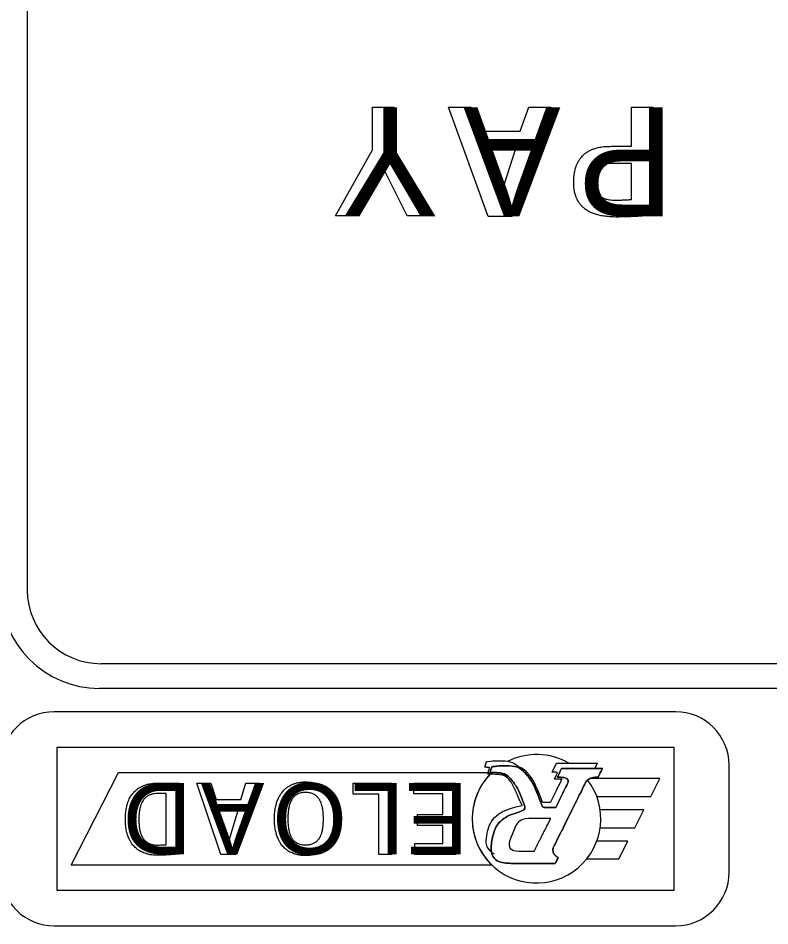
# Model space of a CAD drawing. Extents: x -102643 to -98250, y 54554 to 62384.
# Drawn here: x -102203.2 to -101962.7, y 58225.9 to 58516.5 of the extents above; entities that cross this region are included whole.
import ezdxf

# ---------------------------------------------------------------- set-up
doc = ezdxf.new("R2010")
doc.units = 0
doc.layers.add('SignPanel', color=7, linetype='Continuous')

msp = doc.modelspace()

# ---------------------------------------------------------------- linework, layer by layer
at = {"layer": 'SignPanel'}
for p, q in [((-102200.3, 58701.51), (-102200.3, 58333.46)), ((-101672.5, 58309.8), (-102176.64, 58309.8)), ((-101672.5, 58301.91), (-102177.25, 58301.91)), ((-101992.86, 58294.42), (-102191.66, 58294.41)), ((-101993.32, 58282.99), (-102190.83, 58282.98)), ((-102190.83, 58282.98), (-102190.83, 58237.28)), ((-101993.32, 58237.29), (-101993.32, 58282.99)), ((-101975.72, 58243.01), (-101975.73, 58277.28)), ((-102035.4, 58265.46), (-102032.83, 58265.46)), ((-102190.83, 58237.28), (-101993.32, 58237.29)), ((-102191.66, 58225.86), (-101992.86, 58225.87))]:
    msp.add_line(p, q, dxfattribs=at)
for points in [[(-102089.78, 58474.39), (-102089.78, 58488.01), (-102083.01, 58488.01), (-102083.01, 58474.6), (-102071.07, 58453.17), (-102078.73, 58453.17), (-102086.46, 58468.54), (-102094.22, 58453.17), (-102101.63, 58453.17), (-102089.78, 58474.39)], [(-102058.23, 58488.01), (-102055.48, 58480.35), (-102042.53, 58480.35), (-102039.85, 58488.01), (-102032.74, 58488.01), (-102045.17, 58453.05), (-102052.83, 58453.05), (-102065.46, 58488.01), (-102058.23, 58488.01)], [(-102013.49, 58475.48), (-102006.94, 58475.48), (-102006.94, 58488.01), (-102000.17, 58488.01), (-102000.17, 58453.43)], [(-102049.04, 58459.57), (-102048.87, 58459.56), (-102043.96, 58474.76), (-102053.95, 58474.76), (-102049.04, 58459.57)], [(-102006.94, 58458.43), (-102006.94, 58470.02), (-102012.17, 58470.02)], [(-102053.86, 58276.62), (-102053.34, 58278.44), (-102052.98, 58278.49)], [(-102032.35, 58275.09), (-102030.93, 58277.94), (-102017.9, 58277.94), (-102018.72, 58276.29)], [(-102051.58, 58245.29), (-102186.26, 58245.28), (-102171.13, 58274.99), (-102051.58, 58274.99)], [(-102018.07, 58267.29), (-102000.8, 58267.29), (-101997.89, 58273), (-102020.25, 58273)], [(-102158.44, 58271.56), (-102151.7, 58271.56), (-102151.7, 58248.85)], [(-102141.55, 58271.56), (-102139.89, 58266.34), (-102131.98, 58266.34), (-102130.32, 58271.56), (-102126.02, 58271.56), (-102133.51, 58248.66), (-102138.33, 58248.66), (-102145.98, 58271.56), (-102141.55, 58271.56)], [(-102083.68, 58271.56), (-102083.68, 58248.71), (-102087.79, 58248.71), (-102087.79, 58268.07), (-102095.98, 58268.07), (-102095.98, 58271.56), (-102083.68, 58271.56)], [(-102063.18, 58271.57), (-102063.18, 58248.71), (-102076.26, 58248.71), (-102076.26, 58252.21), (-102067.29, 58252.21), (-102067.29, 58257.96), (-102075.4, 58257.96), (-102075.4, 58261.49), (-102067.29, 58261.49), (-102067.29, 58268.15), (-102076.61, 58268.15), (-102076.61, 58271.56), (-102063.18, 58271.57)], [(-102155.81, 58251.85), (-102155.81, 58268.2)], [(-102016.99, 58257.29), (-102005.9, 58257.29), (-102002.98, 58263), (-102016.99, 58263)], [(-102135.98, 58252.54), (-102135.87, 58252.54), (-102132.81, 58262.9), (-102139.04, 58262.9), (-102135.98, 58252.54)], [(-102021.3, 58247.29), (-102010.99, 58247.29), (-102008.08, 58253), (-102018.07, 58253)]]:
    msp.add_lwpolyline(points, dxfattribs=at)
for centre, radius, start, end in [((-102177.25, 58333.46), 31.55, 180, 270), ((-102176.64, 58333.46), 23.66, 180, 270), ((-102191.66, 58277.27), 17.14, 90.003, 180.003), ((-101992.86, 58277.28), 17.14, 0.003, 90.003), ((-102037.35, 58260.14), 20.57, 59.9596, 116.902), ((-102037.35, 58260.14), 20.57, 136.1816, 226.2418), ((-102037.35, 58260.14), 20.57, 136.1816, 37.2738), ((-102191.66, 58243), 17.14, 180.003, 270.003), ((-101992.86, 58243.01), 17.14, 270.003, 0.003)]:
    msp.add_arc(centre, radius, start, end, dxfattribs=at)
for points, degree in [([(-102025.44, 58463.95), (-102025.43, 58464.39), (-102025.41, 58465.63), (-102025.18, 58467.26), (-102024.83, 58468.59), (-102024.53, 58469.47), (-102024.17, 58470.29), (-102023.63, 58471.21), (-102023.11, 58471.91), (-102022.64, 58472.42), (-102022.14, 58472.91), (-102021.44, 58473.46), (-102020.5, 58474.04), (-102019.65, 58474.43), (-102018.72, 58474.78), (-102017.26, 58475.2), (-102015.42, 58475.45), (-102014, 58475.47), (-102013.49, 58475.48)], 3), ([(-102012.17, 58470.02), (-102012.64, 58470.01), (-102013.54, 58470), (-102014.53, 58469.9), (-102015.23, 58469.79), (-102015.69, 58469.67), (-102016.2, 58469.48), (-102016.59, 58469.27), (-102016.88, 58469.08), (-102017.15, 58468.87), (-102017.46, 58468.55), (-102017.78, 58468.1), (-102018, 58467.67), (-102018.15, 58467.29), (-102018.29, 58466.87), (-102018.46, 58466.13), (-102018.57, 58465.16), (-102018.58, 58464.44), (-102018.58, 58464.12)], 3), ([(-102011.73, 58452.84), (-102012.19, 58452.84), (-102013.56, 58452.86), (-102015.35, 58453.04), (-102017.07, 58453.34), (-102018.48, 58453.69), (-102019.79, 58454.19), (-102020.82, 58454.75), (-102021.46, 58455.16), (-102022.06, 58455.61), (-102022.76, 58456.24), (-102023.49, 58457.1), (-102024.02, 58457.9), (-102024.39, 58458.59), (-102024.73, 58459.33), (-102025.06, 58460.36), (-102025.38, 58461.97), (-102025.42, 58463.19), (-102025.44, 58463.95)], 3), ([(-102018.58, 58464.12), (-102018.58, 58463.85), (-102018.57, 58463.12), (-102018.46, 58462.18), (-102018.27, 58461.43), (-102018.11, 58460.97), (-102017.92, 58460.55), (-102017.63, 58460.1), (-102017.34, 58459.76), (-102017.08, 58459.53), (-102016.8, 58459.3), (-102016.41, 58459.06), (-102015.89, 58458.81), (-102015.41, 58458.65), (-102014.89, 58458.52), (-102014.06, 58458.36), (-102013.02, 58458.27), (-102012.22, 58458.26), (-102011.92, 58458.25)], 3), ([(-102011.92, 58458.25), (-102011.53, 58458.26), (-102010.74, 58458.26), (-102009.52, 58458.31), (-102008.25, 58458.36), (-102007.38, 58458.41), (-102006.94, 58458.43)], 3), ([(-102000.17, 58453.43), (-102001, 58453.35), (-102002.78, 58453.18), (-102005.6, 58453), (-102008.62, 58452.86), (-102010.69, 58452.84), (-102011.73, 58452.84)], 3), ([(-102052.98, 58278.49), (-102051.5, 58278.69), (-102050.55, 58278.74), (-102049.45, 58278.74), (-102046.63, 58278.74), (-102044.65, 58278.11), (-102043.11, 58276.82)], 3), ([(-102052.34, 58276.56), (-102052.84, 58276.6), (-102053.35, 58276.62), (-102053.86, 58276.62)], 2), ([(-102045.24, 58271.5), (-102045.42, 58271.76), (-102045.61, 58272.02), (-102045.8, 58272.25), (-102047.18, 58273.97), (-102049.56, 58274.39), (-102052.96, 58274.39), (-102052.96, 58274.39), (-102052.59, 58275.7), (-102052.34, 58276.56)], 3), ([(-102031.17, 58263.8), (-102031.17, 58263.8), (-102027.68, 58270.85), (-102027.68, 58270.85), (-102027.05, 58271.88), (-102027.5, 58273.44), (-102030.7, 58273.44), (-102030.7, 58273.44), (-102029.27, 58276.29), (-102029.27, 58276.29), (-102029.27, 58276.29), (-102016.24, 58276.29), (-102016.24, 58276.29), (-102016.24, 58276.29), (-102017.66, 58273.44), (-102017.66, 58273.44), (-102017.66, 58273.44), (-102018.07, 58273.44), (-102018.07, 58273.44), (-102018.07, 58273.44), (-102018.51, 58273.42), (-102018.51, 58273.42), (-102018.51, 58273.42), (-102018.88, 58273.38), (-102018.88, 58273.38), (-102018.88, 58273.38), (-102019.51, 58273.24), (-102019.51, 58273.24), (-102019.51, 58273.24), (-102019.99, 58273.11), (-102019.99, 58273.11), (-102019.99, 58273.11), (-102020.4, 58272.94), (-102020.4, 58272.94), (-102020.4, 58272.94), (-102020.69, 58272.78), (-102020.69, 58272.78), (-102020.69, 58272.78), (-102020.98, 58272.61), (-102020.98, 58272.61), (-102020.98, 58272.61), (-102021.27, 58272.34), (-102021.27, 58272.34), (-102021.27, 58272.34), (-102021.48, 58272.07), (-102021.48, 58272.07), (-102021.48, 58272.07), (-102021.55, 58271.91), (-102021.55, 58271.91), (-102021.55, 58271.91), (-102032.03, 58250.8), (-102032.03, 58250.8), (-102032.03, 58250.8), (-102032.07, 58250.5), (-102032.07, 58250.5), (-102032.07, 58250.5), (-102032.07, 58250.21), (-102032.07, 58250.21), (-102032.07, 58250.21), (-102032.07, 58249.99), (-102032.07, 58249.99), (-102032.07, 58249.99), (-102032.05, 58249.72), (-102032.05, 58249.72), (-102032.05, 58249.72), (-102031.97, 58249.4), (-102031.97, 58249.4), (-102031.97, 58249.4), (-102031.84, 58249.05), (-102031.84, 58249.05), (-102031.84, 58249.05), (-102031.7, 58248.82), (-102031.7, 58248.82), (-102031.7, 58248.82), (-102031.45, 58248.49), (-102031.45, 58248.49), (-102031.45, 58248.49), (-102031.11, 58248.2), (-102031.11, 58248.2), (-102031.11, 58248.2), (-102030.76, 58247.95), (-102030.76, 58247.95), (-102030.76, 58247.95), (-102030.41, 58247.74), (-102030.41, 58247.74), (-102030.41, 58247.74), (-102031.36, 58245.87), (-102031.36, 58245.87), (-102031.36, 58245.87), (-102044.17, 58245.87), (-102044.17, 58245.87), (-102049.99, 58245.87), (-102052.32, 58249.4), (-102051.51, 58253.52), (-102050.6, 58258.1), (-102046.22, 58261.68), (-102040.25, 58262.72), (-102041.55, 58265.15), (-102043.12, 58269.83), (-102045.35, 58272.61), (-102046.86, 58274.5), (-102049.51, 58274.96), (-102052.2, 58274.96), (-102052.2, 58274.96), (-102051.68, 58276.78), (-102051.68, 58276.78), (-102051.68, 58276.78), (-102051.32, 58276.83), (-102051.32, 58276.83), (-102049.84, 58277.03), (-102048.89, 58277.08), (-102047.8, 58277.08), (-102044.17, 58277.08), (-102041.94, 58276.04), (-102040.22, 58273.9), (-102038.23, 58271.42), (-102036.3, 58266.12), (-102035.34, 58263.8), (-102035.34, 58263.8), (-102031.17, 58263.8), (-102031.17, 58263.8)], 3), ([(-102031.17, 58263.8), (-102031.17, 58263.8), (-102027.68, 58270.85), (-102027.68, 58270.85), (-102027.05, 58271.88), (-102027.5, 58273.44), (-102030.7, 58273.44), (-102030.7, 58273.44), (-102029.27, 58276.29), (-102029.27, 58276.29), (-102029.27, 58276.29), (-102016.24, 58276.29), (-102016.24, 58276.29), (-102016.24, 58276.29), (-102017.66, 58273.44), (-102017.66, 58273.44), (-102017.66, 58273.44), (-102018.07, 58273.44), (-102018.07, 58273.44), (-102018.07, 58273.44), (-102018.51, 58273.42), (-102018.51, 58273.42), (-102018.51, 58273.42), (-102018.88, 58273.38), (-102018.88, 58273.38), (-102018.88, 58273.38), (-102019.51, 58273.24), (-102019.51, 58273.24), (-102019.51, 58273.24), (-102019.99, 58273.11), (-102019.99, 58273.11), (-102019.99, 58273.11), (-102020.4, 58272.94), (-102020.4, 58272.94), (-102020.4, 58272.94), (-102020.69, 58272.78), (-102020.69, 58272.78), (-102020.69, 58272.78), (-102020.98, 58272.61), (-102020.98, 58272.61), (-102020.98, 58272.61), (-102021.27, 58272.34), (-102021.27, 58272.34), (-102021.27, 58272.34), (-102021.48, 58272.07), (-102021.48, 58272.07), (-102021.48, 58272.07), (-102021.55, 58271.91), (-102021.55, 58271.91), (-102021.55, 58271.91), (-102032.03, 58250.8), (-102032.03, 58250.8), (-102032.03, 58250.8), (-102032.07, 58250.5), (-102032.07, 58250.5), (-102032.07, 58250.5), (-102032.07, 58250.21), (-102032.07, 58250.21), (-102032.07, 58250.21), (-102032.07, 58249.99), (-102032.07, 58249.99), (-102032.07, 58249.99), (-102032.05, 58249.72), (-102032.05, 58249.72), (-102032.05, 58249.72), (-102031.97, 58249.4), (-102031.97, 58249.4), (-102031.97, 58249.4), (-102031.84, 58249.05), (-102031.84, 58249.05), (-102031.84, 58249.05), (-102031.7, 58248.82), (-102031.7, 58248.82), (-102031.7, 58248.82), (-102031.45, 58248.49), (-102031.45, 58248.49), (-102031.45, 58248.49), (-102031.11, 58248.2), (-102031.11, 58248.2), (-102031.11, 58248.2), (-102030.76, 58247.95), (-102030.76, 58247.95), (-102030.76, 58247.95), (-102030.41, 58247.74), (-102030.41, 58247.74), (-102030.41, 58247.74), (-102031.36, 58245.87), (-102031.36, 58245.87), (-102031.36, 58245.87), (-102044.17, 58245.87), (-102044.17, 58245.87), (-102049.99, 58245.87), (-102052.32, 58249.4), (-102051.51, 58253.52), (-102050.6, 58258.1), (-102046.22, 58261.68), (-102040.25, 58262.72), (-102041.55, 58265.15), (-102043.12, 58269.83), (-102045.35, 58272.61), (-102046.86, 58274.5), (-102049.51, 58274.96), (-102052.2, 58274.96), (-102052.2, 58274.96), (-102051.68, 58276.78), (-102051.68, 58276.78), (-102051.68, 58276.78), (-102051.32, 58276.83), (-102051.32, 58276.83), (-102049.84, 58277.03), (-102048.89, 58277.08), (-102047.8, 58277.08), (-102044.17, 58277.08), (-102041.94, 58276.04), (-102040.22, 58273.9), (-102038.23, 58271.42), (-102036.3, 58266.12), (-102035.34, 58263.8), (-102035.34, 58263.8), (-102031.17, 58263.8), (-102031.17, 58263.8)], 3), ([(-102029.46, 58255.99), (-102030.94, 58253), (-102032.03, 58250.8), (-102032.03, 58250.8), (-102032.03, 58250.8), (-102032.07, 58250.5), (-102032.07, 58250.5), (-102032.07, 58250.5), (-102032.07, 58250.21), (-102032.07, 58250.21), (-102032.07, 58250.21), (-102032.07, 58249.99), (-102032.07, 58249.99), (-102032.07, 58249.99), (-102032.05, 58249.72), (-102032.05, 58249.72), (-102032.05, 58249.72), (-102031.97, 58249.4), (-102031.97, 58249.4), (-102031.97, 58249.4), (-102031.84, 58249.05), (-102031.84, 58249.05), (-102031.84, 58249.05), (-102031.7, 58248.82), (-102031.7, 58248.82), (-102031.7, 58248.82), (-102031.45, 58248.49), (-102031.45, 58248.49), (-102031.45, 58248.49), (-102031.11, 58248.2), (-102031.11, 58248.2), (-102031.11, 58248.2), (-102030.76, 58247.95), (-102030.76, 58247.95), (-102030.76, 58247.95), (-102030.41, 58247.74), (-102030.41, 58247.74), (-102030.41, 58247.74), (-102031.36, 58245.87), (-102031.36, 58245.87), (-102031.36, 58245.87), (-102044.17, 58245.87), (-102044.17, 58245.87), (-102049.99, 58245.87), (-102052.32, 58249.4), (-102051.51, 58253.52), (-102050.6, 58258.1), (-102046.22, 58261.68), (-102040.25, 58262.72), (-102041.55, 58265.15), (-102043.12, 58269.83), (-102045.35, 58272.61), (-102046.86, 58274.5), (-102049.51, 58274.96), (-102052.2, 58274.96), (-102052.2, 58274.96), (-102051.68, 58276.78), (-102051.68, 58276.78), (-102051.68, 58276.78), (-102051.32, 58276.83), (-102051.32, 58276.83), (-102049.84, 58277.03), (-102048.89, 58277.08), (-102047.8, 58277.08), (-102044.17, 58277.08), (-102041.94, 58276.04), (-102040.22, 58273.9), (-102038.23, 58271.42), (-102036.3, 58266.12), (-102035.34, 58263.8), (-102035.34, 58263.8), (-102031.17, 58263.8), (-102031.17, 58263.8)], 3), ([(-102051.76, 58276.5), (-102051.91, 58275.99), (-102052.2, 58274.96), (-102052.2, 58274.96), (-102050.14, 58274.96), (-102048.11, 58274.69), (-102046.59, 58273.72)], 3), ([(-102035.4, 58265.46), (-102036.36, 58267.87), (-102038.03, 58272.08), (-102039.78, 58274.26), (-102040.69, 58275.39), (-102041.77, 58276.25), (-102043.11, 58276.82)], 3), ([(-102041.76, 58275.41), (-102041.2, 58274.99), (-102040.69, 58274.49), (-102040.22, 58273.9), (-102038.62, 58271.9), (-102037.06, 58268.08), (-102036.01, 58265.46)], 3), ([(-102030.61, 58274.88), (-102031.07, 58275.02), (-102031.64, 58275.09), (-102032.35, 58275.09)], 2), ([(-102029.25, 58272.67), (-102029.8, 58272.79), (-102030.58, 58272.86), (-102031.62, 58272.86), (-102031.62, 58272.86), (-102031.11, 58273.88), (-102030.61, 58274.88)], 3), ([(-102031.17, 58263.8), (-102031.17, 58263.8), (-102027.68, 58270.85), (-102027.68, 58270.85), (-102027.05, 58271.88), (-102027.5, 58273.44), (-102030.7, 58273.44), (-102030.7, 58273.44), (-102029.27, 58276.29), (-102029.27, 58276.29), (-102029.27, 58276.29), (-102016.24, 58276.29), (-102016.24, 58276.29), (-102016.24, 58276.29), (-102017.66, 58273.44), (-102017.66, 58273.44), (-102017.66, 58273.44), (-102018.07, 58273.44), (-102018.07, 58273.44), (-102018.07, 58273.44), (-102018.51, 58273.42), (-102018.51, 58273.42), (-102018.51, 58273.42), (-102018.88, 58273.38), (-102018.88, 58273.38), (-102018.88, 58273.38), (-102019.51, 58273.24), (-102019.51, 58273.24), (-102019.51, 58273.24), (-102019.99, 58273.11), (-102019.99, 58273.11), (-102019.99, 58273.11), (-102020.4, 58272.94), (-102020.4, 58272.94), (-102020.4, 58272.94), (-102020.69, 58272.78), (-102020.69, 58272.78), (-102020.69, 58272.78), (-102020.98, 58272.61), (-102020.98, 58272.61), (-102020.98, 58272.61), (-102021.27, 58272.34), (-102021.27, 58272.34), (-102021.27, 58272.34), (-102021.48, 58272.07), (-102021.48, 58272.07), (-102021.48, 58272.07), (-102021.55, 58271.91), (-102021.55, 58271.91), (-102021.55, 58271.91), (-102026.33, 58262.29), (-102029.44, 58256.03)], 3), ([(-102030.07, 58274.68), (-102030.4, 58274.03), (-102030.7, 58273.44), (-102030.7, 58273.44), (-102030.06, 58273.44), (-102029.53, 58273.37), (-102029.09, 58273.27)], 3), ([(-102121.21, 58260.12), (-102121.2, 58260.56), (-102121.18, 58261.82), (-102120.97, 58263.47), (-102120.59, 58265.01), (-102120.18, 58266.22), (-102119.65, 58267.34), (-102119.08, 58268.21), (-102118.67, 58268.74), (-102118.24, 58269.24), (-102117.64, 58269.81), (-102116.86, 58270.41), (-102116.14, 58270.83), (-102115.54, 58271.12), (-102114.9, 58271.39), (-102113.87, 58271.7), (-102112.58, 58271.92), (-102111.63, 58271.94), (-102111.23, 58271.95)], 3), ([(-102111.23, 58271.95), (-102110.83, 58271.94), (-102109.87, 58271.92), (-102108.58, 58271.7), (-102107.54, 58271.39), (-102106.9, 58271.12), (-102106.3, 58270.83), (-102105.58, 58270.41), (-102104.8, 58269.81), (-102104.21, 58269.24), (-102103.78, 58268.74), (-102103.37, 58268.21), (-102102.81, 58267.34), (-102102.28, 58266.22), (-102101.87, 58265.01), (-102101.49, 58263.47), (-102101.28, 58261.83), (-102101.26, 58260.56), (-102101.25, 58260.12)], 3), ([(-102032.83, 58265.46), (-102032.83, 58265.46), (-102029.34, 58272.51), (-102029.34, 58272.51), (-102029.31, 58272.56), (-102029.28, 58272.61), (-102029.25, 58272.67)], 3), ([(-102168.89, 58260.02), (-102168.88, 58260.46), (-102168.86, 58261.7), (-102168.65, 58263.31), (-102168.28, 58264.82), (-102167.99, 58265.69), (-102167.64, 58266.5), (-102167.24, 58267.25), (-102166.76, 58267.95), (-102166.34, 58268.47), (-102165.89, 58268.95), (-102165.28, 58269.51), (-102164.45, 58270.08), (-102163.71, 58270.49), (-102163.07, 58270.77), (-102162.39, 58271.02), (-102161.28, 58271.33), (-102159.9, 58271.53), (-102158.87, 58271.55), (-102158.44, 58271.56)], 3), ([(-102041.9, 58264.38), (-102042.84, 58266.12), (-102043.9, 58269), (-102045.25, 58271.52)], 2), ([(-102158.15, 58268.27), (-102158.41, 58268.26), (-102159.14, 58268.25), (-102159.98, 58268.12), (-102160.64, 58267.93), (-102160.95, 58267.83), (-102161.34, 58267.67), (-102161.8, 58267.42), (-102162.31, 58267.06), (-102162.69, 58266.7), (-102162.97, 58266.38), (-102163.23, 58266.03), (-102163.59, 58265.44), (-102163.93, 58264.65), (-102164.19, 58263.78), (-102164.44, 58262.61), (-102164.57, 58261.31), (-102164.58, 58260.29), (-102164.59, 58259.92)], 3), ([(-102155.81, 58268.2), (-102156.04, 58268.21), (-102156.46, 58268.24), (-102157.05, 58268.26), (-102157.61, 58268.27), (-102157.97, 58268.27), (-102158.15, 58268.27)], 3), ([(-102111.26, 58268.56), (-102111.4, 58268.56), (-102111.78, 58268.56), (-102112.4, 58268.49), (-102113.1, 58268.33), (-102113.62, 58268.13), (-102114.01, 58267.93), (-102114.36, 58267.71), (-102114.77, 58267.39), (-102115.21, 58266.94), (-102115.52, 58266.52), (-102115.8, 58266.06), (-102116.16, 58265.35), (-102116.46, 58264.44), (-102116.71, 58263.2), (-102116.87, 58261.83), (-102116.9, 58260.7), (-102116.91, 58260.12)], 3), ([(-102105.52, 58260.12), (-102105.54, 58260.71), (-102105.56, 58261.84), (-102105.72, 58263.22), (-102105.98, 58264.46), (-102106.25, 58265.26), (-102106.55, 58265.89), (-102106.71, 58266.18), (-102106.94, 58266.54), (-102107.26, 58266.96), (-102107.7, 58267.41), (-102108.12, 58267.72), (-102108.47, 58267.94), (-102108.86, 58268.14), (-102109.39, 58268.34), (-102110.09, 58268.49), (-102110.73, 58268.56), (-102111.12, 58268.56), (-102111.26, 58268.56)], 3), ([(-102050.79, 58248.77), (-102052.92, 58250.16), (-102053.68, 58252.55), (-102053.16, 58255.18), (-102052.26, 58259.75), (-102047.87, 58263.33), (-102041.9, 58264.38)], 3), ([(-102111.23, 58248.35), (-102111.63, 58248.36), (-102112.59, 58248.38), (-102113.89, 58248.6), (-102114.93, 58248.92), (-102115.57, 58249.18), (-102116.18, 58249.47), (-102116.89, 58249.89), (-102117.68, 58250.49), (-102118.26, 58251.06), (-102118.69, 58251.56), (-102119.1, 58252.09), (-102119.65, 58252.96), (-102120.18, 58254.07), (-102120.59, 58255.28), (-102120.97, 58256.81), (-102121.18, 58258.43), (-102121.2, 58259.68), (-102121.21, 58260.12)], 3), ([(-102116.91, 58260.12), (-102116.9, 58259.53), (-102116.87, 58258.41), (-102116.71, 58257.03), (-102116.46, 58255.8), (-102116.19, 58255.01), (-102115.89, 58254.39), (-102115.73, 58254.11), (-102115.51, 58253.75), (-102115.19, 58253.34), (-102114.75, 58252.9), (-102114.34, 58252.59), (-102113.99, 58252.38), (-102113.61, 58252.18), (-102113.08, 58251.99), (-102112.39, 58251.84), (-102111.77, 58251.77), (-102111.37, 58251.77), (-102111.24, 58251.77)], 3), ([(-102111.24, 58251.77), (-102111.1, 58251.77), (-102110.71, 58251.77), (-102110.08, 58251.84), (-102109.38, 58251.99), (-102108.85, 58252.19), (-102108.46, 58252.39), (-102108.1, 58252.61), (-102107.69, 58252.92), (-102107.24, 58253.36), (-102106.92, 58253.77), (-102106.7, 58254.13), (-102106.32, 58254.82), (-102106, 58255.71), (-102105.72, 58257.06), (-102105.56, 58258.42), (-102105.54, 58259.54), (-102105.52, 58260.12)], 3), ([(-102101.25, 58260.12), (-102101.26, 58259.68), (-102101.28, 58258.43), (-102101.49, 58256.81), (-102101.87, 58255.28), (-102102.28, 58254.07), (-102102.81, 58252.96), (-102103.36, 58252.09), (-102103.77, 58251.56), (-102104.19, 58251.06), (-102104.78, 58250.49), (-102105.57, 58249.89), (-102106.28, 58249.47), (-102106.89, 58249.18), (-102107.53, 58248.92), (-102108.57, 58248.6), (-102109.87, 58248.38), (-102110.83, 58248.36), (-102111.23, 58248.35)], 3), ([(-102033.83, 58258.21), (-102033.23, 58259.41), (-102032.81, 58260.25), (-102032.81, 58260.25), (-102032.81, 58260.25), (-102034.54, 58260.25), (-102034.54, 58260.25), (-102040.26, 58260.25), (-102043.34, 58259.83), (-102045.27, 58254.86), (-102046.6, 58251.41), (-102045.12, 58249.73), (-102040.85, 58249.73), (-102040.85, 58249.73), (-102038.11, 58249.73), (-102038.11, 58249.73)], 3), ([(-102158.57, 58248.46), (-102158.98, 58248.47), (-102159.96, 58248.49), (-102161.28, 58248.69), (-102162.35, 58248.98), (-102163.01, 58249.22), (-102163.64, 58249.49), (-102164.37, 58249.88), (-102165.19, 58250.44), (-102165.8, 58250.99), (-102166.25, 58251.46), (-102166.67, 58251.97), (-102167.15, 58252.67), (-102167.73, 58253.74), (-102168.19, 58254.94), (-102168.64, 58256.64), (-102168.86, 58258.3), (-102168.88, 58259.57), (-102168.89, 58260.02)], 3), ([(-102164.59, 58259.92), (-102164.58, 58259.4), (-102164.55, 58258.38), (-102164.4, 58257.12), (-102164.17, 58255.94), (-102163.88, 58255.06), (-102163.53, 58254.35), (-102163.26, 58253.88), (-102162.94, 58253.45), (-102162.49, 58252.99), (-102162.07, 58252.66), (-102161.7, 58252.42), (-102161.3, 58252.2), (-102160.74, 58251.98), (-102160, 58251.81), (-102159.33, 58251.74), (-102158.91, 58251.74), (-102158.77, 58251.74)], 3), ([(-102038.11, 58249.73), (-102038.11, 58249.73), (-102035.4, 58255.1), (-102033.85, 58258.17)], 2), ([(-102158.77, 58251.74), (-102158.52, 58251.74), (-102158.03, 58251.74), (-102157.29, 58251.76), (-102156.55, 58251.79), (-102156.06, 58251.83), (-102155.81, 58251.85)], 3), ([(-102151.7, 58248.85), (-102151.96, 58248.82), (-102152.5, 58248.78), (-102153.34, 58248.7), (-102154.2, 58248.62), (-102155.09, 58248.57), (-102155.99, 58248.53), (-102156.88, 58248.49), (-102157.74, 58248.47), (-102158.3, 58248.46), (-102158.57, 58248.46)], 3)]:
    msp.add_open_spline(points, degree=degree, dxfattribs=at)

# ---------------------------------------------------------------- texts
for s, height, rotation, p in [('Y', 34.96, 180, (-102068.62, 58488.01)), ('Y', 34.96, 180, (-102068.62, 58488.01)), ('A', 34.96, 180, (-102029.61, 58488.01)), ('A', 34.96, 180, (-102029.61, 58488.01)), ('P', 34.96, 180, (-101993.18, 58488.01)), ('P', 34.96, 180, (-101993.18, 58488.01)), ('O', 22.85, 180.003, (-102098.06, 58271.56)), ('O', 22.85, 180.003, (-102098.06, 58271.56)), ('D', 22.85, 180.003, (-102147.6, 58271.56)), ('D', 22.85, 180.003, (-102147.6, 58271.56)), ('A', 22.85, 180.003, (-102124.42, 58271.56)), ('A', 22.85, 180.003, (-102124.42, 58271.56)), ('L', 22.85, 180.003, (-102079.57, 58271.56)), ('L', 22.85, 180.003, (-102079.57, 58271.56)), ('E', 22.85, 180.003, (-102059.07, 58271.57)), ('E', 22.85, 180.003, (-102059.07, 58271.57))]:
    msp.add_text(s, height=height, rotation=rotation, dxfattribs=at).set_placement(p)

doc.saveas('drawing.dxf')
